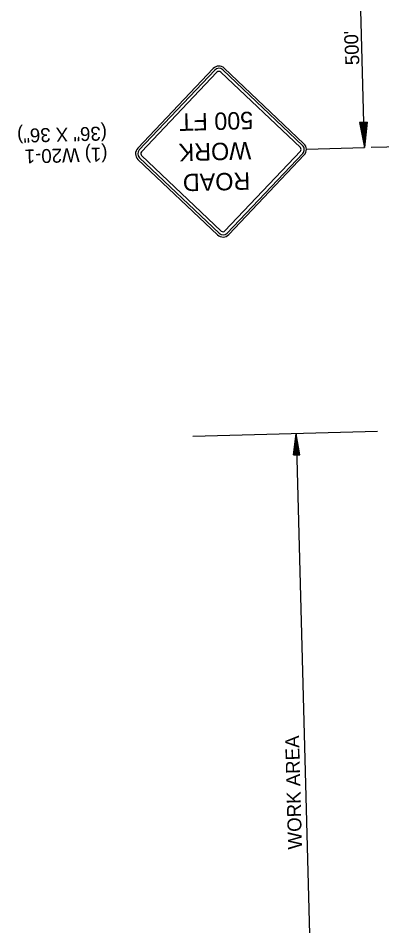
# Model space of a CAD drawing. Extents: x 1930579 to 1931593, y 596452 to 598537.
# Drawn here: x 1930697.1 to 1930853.7, y 597826.5 to 598217.2 of the extents above; entities that cross this region are included whole.
import ezdxf

# ---------------------------------------------------------------- set-up
doc = ezdxf.new("R2010")
doc.units = 0
for name, color, linetype in [('P_TC_Signs_Temporary', 7, 'Continuous'), ('R_Annotation', 7, 'Continuous'), ('R_Draft', 7, 'Continuous')]:
    doc.layers.add(name, color=color, linetype=linetype)

msp = doc.modelspace()

# ---------------------------------------------------------------- linework, layer by layer
at = {"layer": 'P_TC_Signs_Temporary'}
for p, q in [((1930785.87, 598195.61), (1930820.17, 598163.11)), ((1930748.6, 598161.18), (1930781.1, 598195.48)), ((1930749.28, 598160.54), (1930781.78, 598194.83)), ((1930750.23, 598159.64), (1930782.73, 598193.93)), ((1930784.32, 598193.97), (1930818.62, 598161.47)), ((1930785.23, 598194.93), (1930819.52, 598162.42)), ((1930783.67, 598124.59), (1930749.37, 598157.09)), ((1930784.57, 598125.54), (1930750.27, 598158.05)), ((1930818.66, 598159.88), (1930786.16, 598125.59)), ((1930819.61, 598158.98), (1930787.11, 598124.68)), ((1930820.29, 598158.33), (1930787.79, 598124.04)), ((1930783.02, 598123.91), (1930748.73, 598156.41))]:
    msp.add_line(p, q, dxfattribs=at)
for centre, radius, start, end in [((1930783.55, 598193.16), 3.38, 46.5377, 136.5377), ((1930783.55, 598193.16), 2.44, 46.5377, 136.5377), ((1930783.55, 598193.16), 1.13, 46.5377, 136.5377), ((1930751.05, 598158.86), 3.38, 136.5377, 226.5377), ((1930751.05, 598158.86), 2.44, 136.5377, 226.5377), ((1930817.84, 598160.66), 1.12, 316.5377, 46.5377), ((1930817.84, 598160.66), 2.44, 316.5377, 46.5377), ((1930817.84, 598160.66), 3.38, 316.5377, 46.5377), ((1930751.05, 598158.86), 1.12, 136.5377, 226.5377), ((1930785.34, 598126.36), 1.13, 226.5377, 316.5377), ((1930785.34, 598126.36), 3.37, 226.5377, 316.5377), ((1930785.34, 598126.36), 2.44, 226.5377, 316.5377)]:
    msp.add_arc(centre, radius, start, end, dxfattribs=at)
at = {"layer": 'R_Draft'}
for p, q in [((1930846.21, 598161.54), (1930843.52, 598261.5)), ((1930847.37, 598172.48), (1930844.11, 598172.34)), ((1930844.11, 598172.34), (1930846.21, 598161.54)), ((1930844.38, 598172.35), (1930846.13, 598163.36)), ((1930844.66, 598172.36), (1930846.05, 598165.22)), ((1930844.93, 598172.38), (1930845.97, 598167.03)), ((1930845.21, 598172.39), (1930845.89, 598168.88)), ((1930845.48, 598172.4), (1930845.81, 598170.69)), ((1930846, 598172.42), (1930845.81, 598170.69)), ((1930846.27, 598172.43), (1930845.89, 598168.88)), ((1930846.55, 598172.44), (1930845.97, 598167.03)), ((1930846.82, 598172.45), (1930846.05, 598165.22)), ((1930847.1, 598172.47), (1930846.13, 598163.36)), ((1930847.37, 598172.48), (1930846.21, 598161.54)), ((1930821.21, 598160.87), (1930846.21, 598161.54)), ((1930849.07, 598161.62), (1930862.53, 598161.98)), ((1930851.89, 598039.28), (1930772.38, 598037.15)), ((1930815.72, 598029.24), (1930816.84, 598038.34)), ((1930815.95, 598029.25), (1930816.88, 598036.83)), ((1930818.44, 598029.32), (1930816.84, 598038.34)), ((1930816.84, 598038.34), (1930825.1, 597730.33)), ((1930818.21, 598029.31), (1930816.88, 598036.83)), ((1930816.18, 598029.26), (1930816.92, 598035.27)), ((1930816.4, 598029.26), (1930816.96, 598033.76)), ((1930816.64, 598029.27), (1930817, 598032.23)), ((1930817.98, 598029.3), (1930816.92, 598035.27)), ((1930817.75, 598029.3), (1930816.96, 598033.76)), ((1930817.52, 598029.29), (1930817, 598032.23)), ((1930815.72, 598029.24), (1930818.44, 598029.32)), ((1930816.87, 598029.27), (1930817.04, 598030.71)), ((1930817.29, 598029.29), (1930817.04, 598030.71))]:
    msp.add_line(p, q, dxfattribs=at)

# ---------------------------------------------------------------- texts
at = {"layer": 'P_TC_Signs_Temporary'}
for s, p in [('500 FT ', (1930798.2, 598176.97)), ('WORK', (1930797.33, 598163.92)), (' ROAD ', (1930799.71, 598150.95))]:
    msp.add_text(s, height=7.5, rotation=181.5377, dxfattribs=at).set_placement(p)
at = {"layer": 'R_Annotation'}
for s, rotation, p in [('(36" X 36")', 181.5377, (1930735.3, 598170.57)), ('(1) W20-1', 181.5377, (1930735.55, 598161.57)), ('WORK AREA', 91.5377, (1930819.34, 597859.5))]:
    msp.add_text(s, height=6, rotation=rotation, dxfattribs=at).set_placement(p)
at = {"layer": 'R_Draft'}
msp.add_text("500'", height=6, rotation=92.7681, dxfattribs=at).set_placement((1930844.06, 598197.08))

doc.saveas('drawing.dxf')
